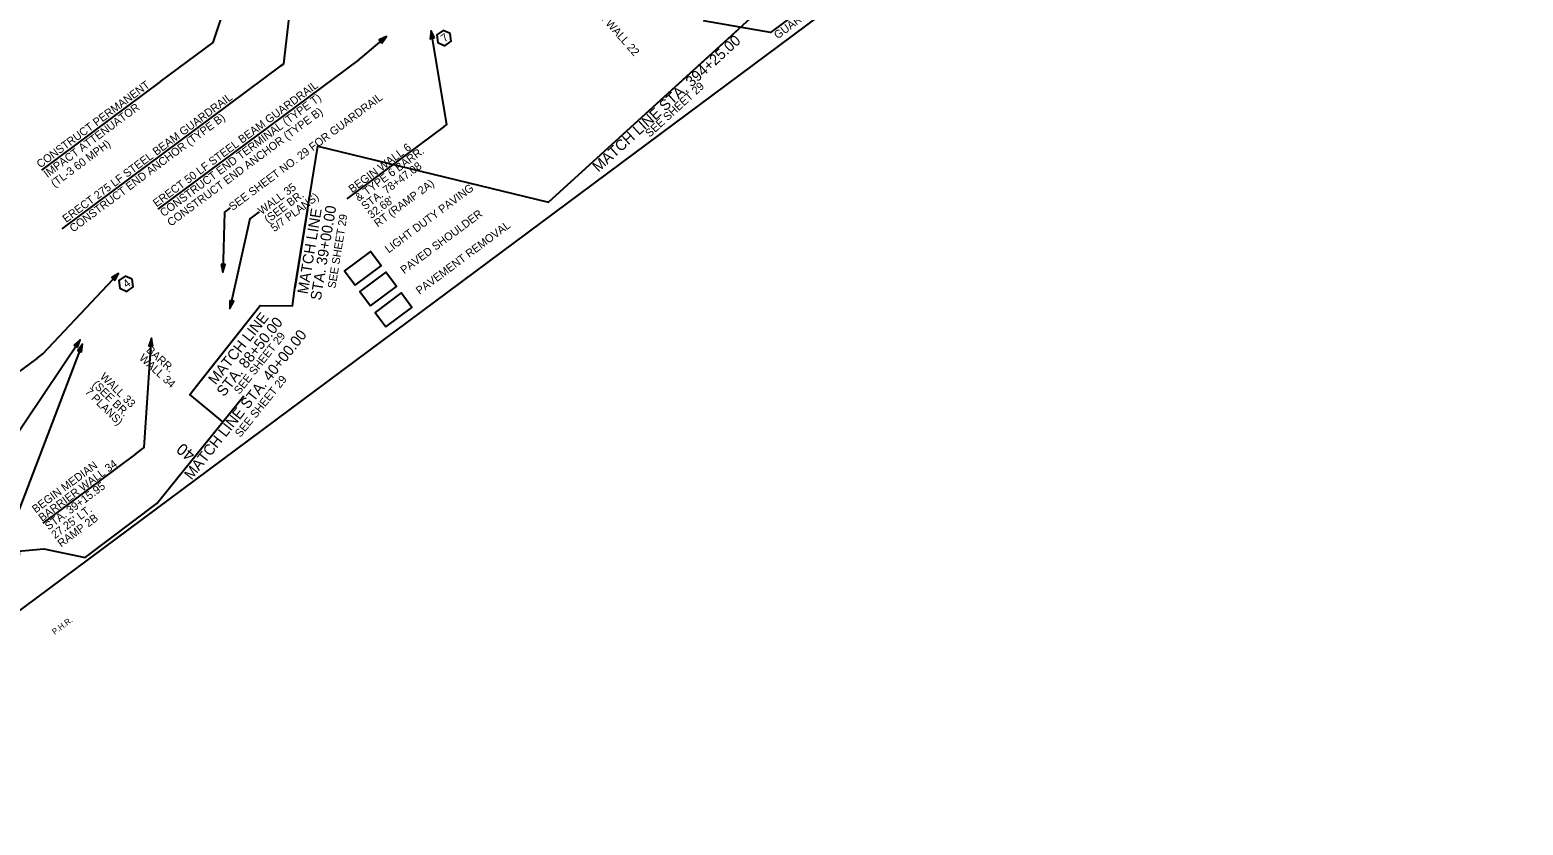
# Model space of a CAD drawing. Extents: x 1609621 to 1611756, y 1093008 to 1094970.
# Drawn here: x 1610636 to 1611756, y 1093025 to 1093621 of the extents above; entities that cross this region are included whole.
import ezdxf

# ---------------------------------------------------------------- set-up
doc = ezdxf.new("R2010")
doc.units = 0
for name, color, linetype in [('Level 2', 7, 'Continuous'), ('Plan_Clip', 7, 'Continuous'), ('RD_HC_TX_Sta50', 7, 'Continuous'), ('RD_PD_GR_TX', 7, 'Continuous'), ('RD_SHT_MatchLine', 7, 'Continuous'), ('RD_SHT_TX', 7, 'Continuous'), ('RD_TX_Bridge', 7, 'Continuous')]:
    doc.layers.add(name, color=color, linetype=linetype)

msp = doc.modelspace()

# ---------------------------------------------------------------- linework, layer by layer
at = {"layer": 'Level 2'}
msp.add_lwpolyline([(1609840.9, 1093793), (1611185.2, 1094792.2), (1611755.8, 1094024.6), (1610411.6, 1093025.3)], close=True, dxfattribs=at)
at = {"layer": 'Plan_Clip'}
msp.add_lwpolyline([(1610334.7, 1093203.9), (1610646.7, 1093232.4), (1610677.6, 1093225.9), (1610731.5, 1093266.4), (1610780.8, 1093327.6), (1610756.1, 1093348.1), (1610808.8, 1093414.8), (1610833.1, 1093414.5), (1610834.8, 1093427.6), (1610852.1, 1093534.1), (1611025, 1093492.1), (1611182.1, 1093635), (1611255.8, 1093702.1), (1611373.3, 1093746.6), (1611408.6, 1093885.5), (1611545.9, 1093852.8), (1611572.3, 1093898.6), (1611738.6, 1094022.9), (1611661.9, 1094095.6), (1611556.8, 1094157.1), (1611573.1, 1094182.9), (1611487.3, 1094233.1), (1611475.5, 1094276), (1611373.3, 1094413.5)], dxfattribs=at)
msp.add_lwpolyline([(1610334.7, 1093203.9), (1610646.7, 1093232.4), (1610677.6, 1093225.9), (1610731.5, 1093266.4), (1610780.8, 1093327.6), (1610756.1, 1093348.1), (1610808.8, 1093414.8), (1610833.1, 1093414.5), (1610834.8, 1093427.6), (1610852.1, 1093534.1), (1611025, 1093492.1), (1611182.1, 1093635), (1611255.8, 1093702.1), (1611373.3, 1093746.6), (1611408.6, 1093885.5), (1611545.9, 1093852.8), (1611572.3, 1093898.6), (1611738.6, 1094022.9), (1611661.9, 1094095.6), (1611556.8, 1094157.1), (1611573.1, 1094182.9), (1611487.3, 1094233.1), (1611475.5, 1094276), (1611373.3, 1094413.5)], dxfattribs=at)
at = {"layer": 'RD_PD_GR_TX'}
for p, q in [((1611267.1, 1093675.6), (1611192.4, 1093620.1)), ((1610823.9, 1093594), (1610660.2, 1093472.3)), ((1610883, 1093599.1), (1610732.1, 1093487)), ((1610734.1, 1093582.5), (1610644.8, 1093516.2))]:
    msp.add_line(p, q, dxfattribs=at)
for points in [[(1610734.1, 1093582.5), (1610773.5, 1093611.9), (1610819.8, 1093749.8)], [(1610823.9, 1093594), (1610826.5, 1093595.9), (1610832.9, 1093650.1)], [(1611192.4, 1093620.1), (1611191.5, 1093619.4), (1611141.2, 1093628)], [(1610883, 1093599.1), (1610885.9, 1093601.3), (1610903.5, 1093616.4)], [(1610786.4, 1093487.9), (1610782.1, 1093484.7), (1610780.9, 1093439.8)]]:
    msp.add_lwpolyline(points, dxfattribs=at)
for points in [[(1610900.1, 1093611.4), (1610903.5, 1093616.4), (1610898.1, 1093613.8)], [(1610779.5, 1093445.6), (1610780.9, 1093439.8), (1610782.6, 1093445.5)]]:
    msp.add_lwpolyline(points, close=True, dxfattribs=at)
at = {"layer": 'RD_SHT_MatchLine'}
for p, q in [((1611166.5, 1093620.9), (1611025, 1093492.1)), ((1610844.4, 1093486.6), (1610834.8, 1093427.6)), ((1610760.3, 1093353.5), (1610808.8, 1093414.8)), ((1610731.5, 1093266.4), (1610796.5, 1093347.1))]:
    msp.add_line(p, q, dxfattribs=at)
at = {"layer": 'RD_SHT_TX'}
for p, q in [((1610946.8, 1093548.8), (1610873.9, 1093494.6)), ((1610641.3, 1093375.1), (1610571.1, 1093322.9)), ((1610715.7, 1093303.5), (1610646, 1093251.6))]:
    msp.add_line(p, q, dxfattribs=at)
for points in [[(1610939.5, 1093615.2), (1610937, 1093620.6), (1610936.4, 1093614.6)], [(1610951.3, 1093618.6), (1610946, 1093620.9), (1610941.3, 1093617.5), (1610942, 1093611.7), (1610947.4, 1093609.4), (1610952, 1093612.8)], [(1610880, 1093430), (1610899.5, 1093444.5), (1610891.5, 1093455.3), (1610872, 1093440.8)], [(1610699.8, 1093433.5), (1610702.7, 1093438.8), (1610697.6, 1093435.7)], [(1610713, 1093434.5), (1610707.7, 1093436.8), (1610703, 1093433.4), (1610703.7, 1093427.6), (1610709, 1093425.3), (1610713.7, 1093428.8)], [(1610891.6, 1093414.4), (1610911.1, 1093428.9), (1610903.1, 1093439.7), (1610883.6, 1093425.2)], [(1610903.2, 1093398.8), (1610922.7, 1093413.3), (1610914.7, 1093424.1), (1610895.2, 1093409.6)], [(1610786, 1093418.5), (1610786.2, 1093412.6), (1610789, 1093417.9)], [(1610728.4, 1093384.3), (1610727.3, 1093390.2), (1610725.3, 1093384.5)], [(1610675, 1093379.8), (1610675.6, 1093385.8), (1610672.1, 1093380.9)]]:
    msp.add_lwpolyline(points, close=True, dxfattribs=at)
for points in [[(1610946.8, 1093548.8), (1610948.8, 1093550.3), (1610937, 1093620.6)], [(1610808.1, 1093484.9), (1610801.1, 1093479.6), (1610786.2, 1093412.6)], [(1610880, 1093430), (1610899.5, 1093444.5), (1610891.5, 1093455.3), (1610872, 1093440.8), (1610880, 1093430)], [(1610641.3, 1093375.1), (1610645.9, 1093378.4), (1610702.7, 1093438.8)], [(1610891.6, 1093414.4), (1610911.1, 1093428.9), (1610903.1, 1093439.7), (1610883.6, 1093425.2), (1610891.6, 1093414.4)], [(1610903.2, 1093398.8), (1610922.7, 1093413.3), (1610914.7, 1093424.1), (1610895.2, 1093409.6), (1610903.2, 1093398.8)], [(1610715.7, 1093303.5), (1610722, 1093308.2), (1610727.3, 1093390.2)], [(1610628.5, 1093227.7), (1610627.3, 1093259.3), (1610675.6, 1093385.8)]]:
    msp.add_lwpolyline(points, dxfattribs=at)
at = {"layer": 'RD_TX_Bridge'}
msp.add_lwpolyline([(1610603, 1093249.8), (1610591.1, 1093266), (1610673.9, 1093389.1)], dxfattribs=at)
msp.add_lwpolyline([(1610672, 1093383.4), (1610673.9, 1093389.1), (1610669.4, 1093385.1)], close=True, dxfattribs=at)

# ---------------------------------------------------------------- texts
at = {"layer": 'RD_HC_TX_Sta50'}
msp.add_text('40', height=8.75, rotation=141.1632, dxfattribs=at).set_placement((1610760.8, 1093304.1))
at = {"layer": 'RD_PD_GR_TX'}
for s, rotation, p in [('GUARDRAIL NOTE', 36.6272, (1611196.9, 1093614.1)), ('CONSTRUCT PERMANENT', 36.6256, (1610644, 1093517.4)), ('ERECT 50 LF STEEL BEAM GUARDRAIL', 36.6272, (1610731.2, 1093488.2)), ('ERECT 275 LF STEEL BEAM GUARDRAIL', 36.6272, (1610663.4, 1093476.5)), ('CONSTRUCT END TERMINAL (TYPE T)', 36.6272, (1610736.5, 1093480.9)), ('SEE SHEET NO. 29 FOR GUARDRAIL', 36.6272, (1610788.2, 1093485.5)), ('IMPACT ATTENUATOR', 36.6256, (1610649.3, 1093510.2)), ('CONSTRUCT END ANCHOR (TYPE B)', 36.6272, (1610668.7, 1093469.3)), ('CONSTRUCT END ANCHOR (TYPE B)', 36.6272, (1610741.9, 1093473.7)), ('(TL-3 60 MPH)', 36.6256, (1610654.7, 1093503))]:
    msp.add_text(s, height=6, rotation=rotation, dxfattribs=at).set_placement(p)
at = {"layer": 'RD_SHT_MatchLine'}
for s, height, rotation, p in [('MATCH LINE STA. 394+25.00', 8, 42.4045, (1611062.5, 1093514.2)), ('SEE SHEET 29', 6, 42.4557, (1611100.9, 1093540.4)), ('MATCH LINE', 8, 80.6197, (1610844.5, 1093422.9)), ('STA. 39+00.00', 8, 80.6197, (1610854.3, 1093418.2)), ('SEE SHEET 29', 6, 80.7664, (1610865.3, 1093427.2)), ('MATCH LINE', 8, 51.4898, (1610775.4, 1093354.8)), ('STA. 88+50.00', 8, 51.4898, (1610781.7, 1093345.9)), ('MATCH LINE STA. 40+00.00', 8, 51.4638, (1610757.4, 1093283.5)), ('SEE SHEET 29', 6, 51.6837, (1610793.3, 1093347.7)), ('SEE SHEET 29', 6, 51.1632, (1610794, 1093315.5))]:
    msp.add_text(s, height=height, rotation=rotation, dxfattribs=at).set_placement(p)
at = {"layer": 'RD_SHT_TX'}
for s, height, rotation, p in [('BARRIER WALL 22', 6, 311.4156, (1611042.4, 1093654.3)), ('7', 6, 36.6256, (1610947.1, 1093611.7)), ('BEGIN WALL 6', 6, 36.6256, (1610877.9, 1093498.8)), ('& TYPE 6 BARR.', 6, 36.6256, (1610882.7, 1093492.4)), ('STA. 78+47.08', 6, 36.6256, (1610887.5, 1093486)), ('WALL 35', 6, 36.6256, (1610810, 1093482.5)), ('RT (RAMP 2A)', 6, 36.6256, (1610897, 1093473.1)), ('LIGHT DUTY PAVING', 6, 36.6256, (1610905.2, 1093453.7)), ('(SEE BR.', 6, 36.6256, (1610814.7, 1093476.1)), ('5/7 PLANS)', 6, 36.6256, (1610819.5, 1093469.6)), ("32.68' ", 6, 36.6256, (1610892.2, 1093479.5)), ('PAVED SHOULDER', 6, 36.6256, (1610916.8, 1093438.1)), ('PAVEMENT REMOVAL', 6, 36.6256, (1610928.4, 1093422.6)), ('4', 6, 36.6256, (1610708.7, 1093427.6)), ('WALL 34', 6, 317.6507, (1610717.6, 1093374.7)), ('BARR.', 6, 317.6507, (1610723, 1093380.6)), ('(SEE BR. ', 6, 315.5515, (1610682.6, 1093355.1)), ('WALL 33', 6, 315.5515, (1610688.3, 1093360.8)), ('7 PLANS)', 6, 315.5515, (1610677, 1093349.4)), ('BEGIN MEDIAN', 6, 36.6256, (1610640.6, 1093258.9)), ('BARRIER WALL 34', 6, 36.6256, (1610645.4, 1093252.5)), ('STA. 39+15.95', 6, 36.6256, (1610650.2, 1093246.1)), ("27.25' LT.", 6, 36.6256, (1610655, 1093239.6)), ('RAMP 2B', 6, 36.6256, (1610659.7, 1093233.2)), ('P.H.R.', 4.4, 36.6256, (1610654.8, 1093167.8))]:
    msp.add_text(s, height=height, rotation=rotation, dxfattribs=at).set_placement(p)

doc.saveas('drawing.dxf')
